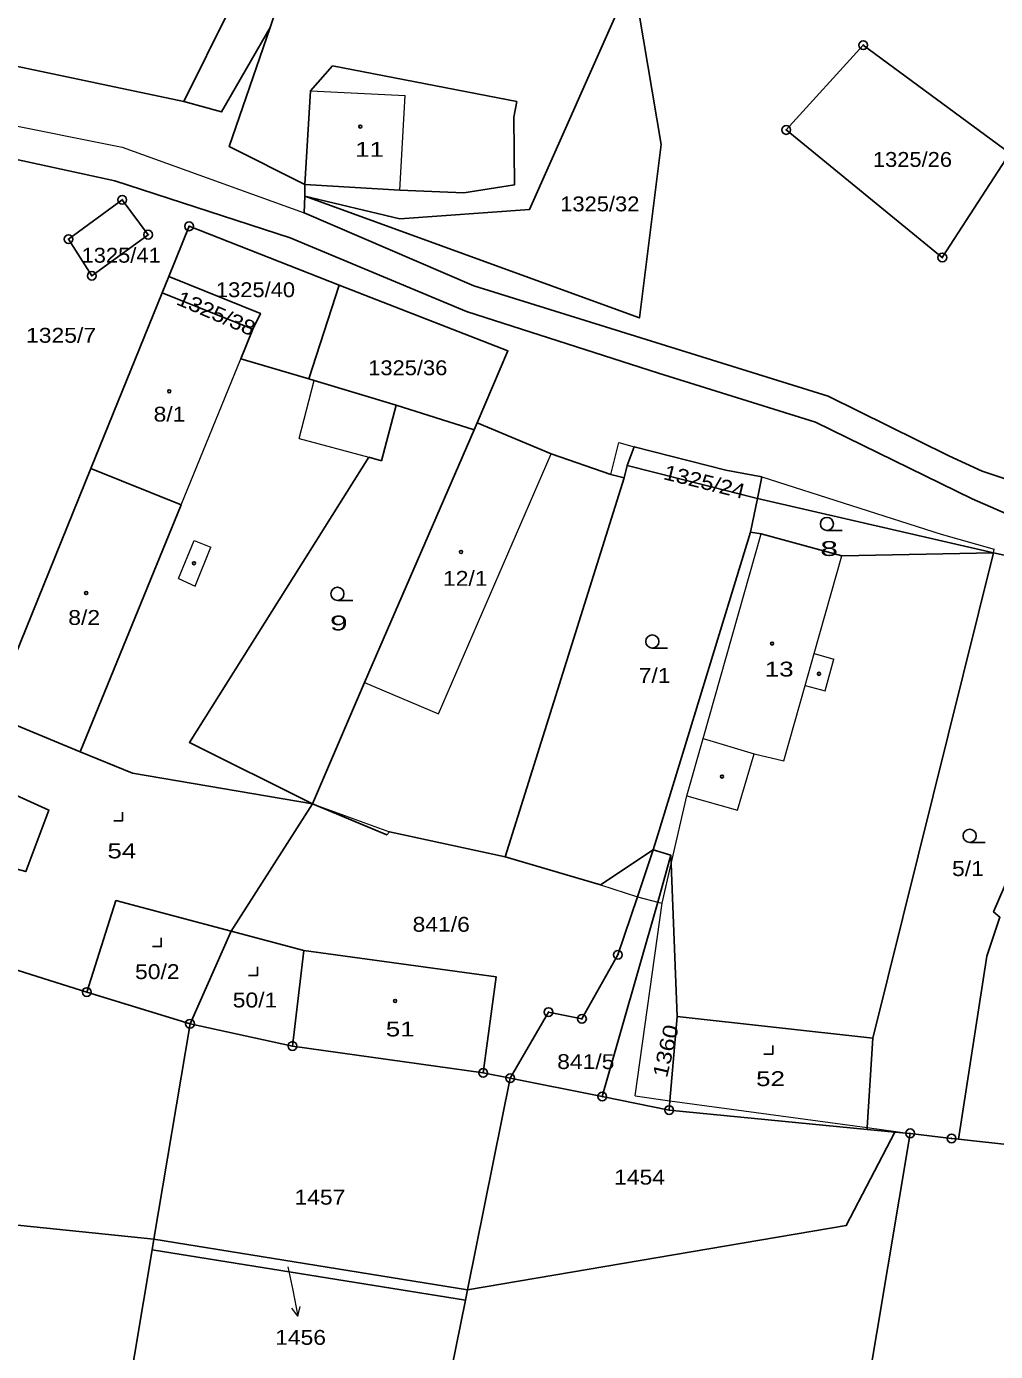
# Model space of a CAD drawing. Extents: x -872229 to -869198, y -1075981 to -1074329.
# Drawn here: x -871035 to -870924.3, y -1075369.5 to -1075218 of the extents above; entities that cross this region are included whole.
import ezdxf
from ezdxf.enums import TextEntityAlignment as Align

# ---------------------------------------------------------------- set-up
doc = ezdxf.new("R2010")
doc.units = 0
doc.header["$LTSCALE"] = 0.68
for name, color, linetype, lineweight in [('1', 7, 'Continuous', 25), ('3', 7, 'Continuous', 25), ('4', 7, 'Continuous', 13), ('5', 7, 'Continuous', 25), ('7', 7, 'Continuous', 13), ('8', 7, 'Continuous', 25)]:
    doc.layers.add(name, color=color, linetype=linetype, lineweight=lineweight)
doc.layers.add('2', color=7, linetype='Continuous')

msp = doc.modelspace()

# ---------------------------------------------------------------- linework, layer by layer
at = {"layer": '1'}
for p, q in [((-871016.45, -1075240.85), (-870999.29, -1075247.56)), ((-870992.78, -1075261.29), (-870994.47, -1075267.64)), ((-870983.88, -1075264.11), (-870983.54, -1075263.33)), ((-870994.47, -1075267.64), (-870995.91, -1075267.25)), ((-870966.4, -1075268.2), (-870966.72, -1075269.58)), ((-870966.4, -1075268.2), (-870951.52, -1075271.96)), ((-871027.67, -1075268.54), (-871039.08, -1075296.69)), ((-870910.7, -1075281.16), (-870924.55, -1075278.18)), ((-871011.62, -1075321.4), (-871002.34, -1075306.85)), ((-870961.39, -1075312.74), (-870963.43, -1075312.12)), ((-871028.14, -1075328.37), (-871016.34, -1075331.99)), ((-871016.34, -1075331.99), (-871020.46, -1075356.63)), ((-871004.64, -1075334.54), (-870982.84, -1075337.6)), ((-870982.84, -1075337.6), (-870979.75, -1075338.22)), ((-870979.75, -1075338.22), (-870984.62, -1075362.41)), ((-870979.75, -1075338.22), (-870969.24, -1075340.31)), ((-870935.8, -1075344.38), (-870938.97, -1075344.07)), ((-870934.07, -1075344.52), (-870935.8, -1075344.38)), ((-870921.99, -1075345.91), (-870928.54, -1075345.19))]:
    msp.add_line(p, q, dxfattribs=at)
for points in [[(-871001.53, -1075179.18), (-871004.71, -1075177.87), (-871056.06, -1075184.2), (-871061.68, -1075207.72), (-871062.03, -1075210.19), (-871063.04, -1075217.35), (-871059.26, -1075218.39), (-871047.62, -1075220.14), (-871017.06, -1075226.57)], [(-871017.06, -1075226.57), (-871011.81, -1075216.07), (-871003.35, -1075187.3), (-871001.53, -1075179.18)], [(-871007.2, -1075218.13), (-871001.24, -1075200.4), (-870998.8, -1075193.31)], [(-871003.22, -1075237.41), (-870964.99, -1075251.33), (-870962.5, -1075231.49), (-870966.06, -1075210.48)], [(-870966.06, -1075210.48), (-870966.78, -1075214.64), (-870977.55, -1075238.93), (-870992.35, -1075240.01), (-871003.22, -1075237.41)], [(-871017.06, -1075226.57), (-871012.74, -1075227.78), (-871007.2, -1075218.13)], [(-871003.22, -1075237.41), (-871003.21, -1075236.08), (-871011.88, -1075231.73), (-871007.2, -1075218.13)], [(-870992.35, -1075236.73), (-870985.06, -1075237.04), (-870979.25, -1075236.1), (-870979.36, -1075228.37), (-870979.01, -1075226.59), (-871000.06, -1075222.52), (-871002.59, -1075225.35)], [(-871002.59, -1075225.35), (-871003.21, -1075236.08), (-870992.35, -1075236.73)], [(-871072.01, -1075232.97), (-871066.83, -1075229.86), (-871050.73, -1075230.05), (-871024.91, -1075235.65), (-871004.91, -1075242.17), (-870984.75, -1075250.58), (-870962.8, -1075257.63), (-870944.86, -1075263.23), (-870926.98, -1075271.99), (-870918.87, -1075275.55), (-870910.63, -1075280.9)], [(-871003.22, -1075237.41), (-871003.31, -1075239.31), (-870983.9, -1075247.65), (-870943.43, -1075260.27), (-870929.66, -1075267.08), (-870925.85, -1075268.83), (-870908.47, -1075274.58)], [(-871027.67, -1075268.54), (-871019.53, -1075248.45), (-871018.75, -1075246.57), (-871016.45, -1075240.85)], [(-871009.17, -1075252.62), (-871008.29, -1075250.81), (-871018.75, -1075246.57)], [(-871002.78, -1075258.3), (-871010.54, -1075255.98), (-871009.17, -1075252.62), (-871019.53, -1075248.45)], [(-870983.54, -1075263.33), (-870980.02, -1075255.1), (-870999.29, -1075247.56), (-871002.78, -1075258.3)], [(-871002.78, -1075258.3), (-871002.16, -1075258.48), (-870992.78, -1075261.29), (-870983.88, -1075264.11)], [(-870968.25, -1075269.2), (-870975.06, -1075266.86), (-870983.54, -1075263.33)], [(-870983.88, -1075264.11), (-870996.4, -1075292.99), (-871002.34, -1075306.85)], [(-870951.52, -1075271.96), (-870951.02, -1075269.49), (-870955.13, -1075268.72), (-870965.59, -1075266.04), (-870966.4, -1075268.2)], [(-870995.91, -1075267.25), (-871016.41, -1075299.83), (-871002.34, -1075306.85)], [(-871028.88, -1075300.9), (-871017.36, -1075272.69), (-871027.67, -1075268.54)], [(-870980.32, -1075312.91), (-870966.72, -1075269.58), (-870968.25, -1075269.2)], [(-870924.55, -1075278.18), (-870951.52, -1075271.96), (-870952.29, -1075275.8)], [(-870952.29, -1075275.8), (-870962.91, -1075310.4), (-870963.43, -1075312.12)], [(-870952.29, -1075275.8), (-870951.09, -1075275.99), (-870941.86, -1075278.5), (-870924.55, -1075278.18)], [(-870961.39, -1075312.74), (-870961.35, -1075313.72), (-870960.69, -1075331.15), (-870938.31, -1075333.64), (-870924.55, -1075278.18)], [(-871028.88, -1075300.9), (-871039.08, -1075296.69), (-871041.74, -1075303.38)], [(-871002.34, -1075306.85), (-871022.9, -1075303.35), (-871028.88, -1075300.9)], [(-871041.74, -1075303.38), (-871032.46, -1075307.57), (-871035.1, -1075314.6), (-871039.25, -1075313.47), (-871042.54, -1075323.84), (-871028.14, -1075328.37)], [(-870980.32, -1075312.91), (-870993.53, -1075310.04), (-870993.87, -1075310.41), (-871002.34, -1075306.85)], [(-870919.9, -1075308.44), (-870924.53, -1075319.22), (-870923.81, -1075319.83), (-870925.29, -1075324.27), (-870928.54, -1075345.19)], [(-870963.43, -1075312.12), (-870969.45, -1075316.11), (-870980.32, -1075312.91)], [(-870979.75, -1075338.22), (-870975.38, -1075330.66), (-870971.56, -1075331.43), (-870967.45, -1075324.11), (-870965.22, -1075317.48), (-870963.43, -1075312.12)], [(-870969.24, -1075340.31), (-870962.91, -1075318.08), (-870961.39, -1075312.74)], [(-871011.62, -1075321.4), (-871024.8, -1075317.92), (-871028.14, -1075328.37)], [(-870982.84, -1075337.6), (-870981.38, -1075326.63), (-871003.32, -1075323.62)], [(-870960.69, -1075331.15), (-870961.51, -1075340.79), (-870961.6, -1075341.86)], [(-870938.97, -1075344.07), (-870938.96, -1075343.86), (-870938.31, -1075333.64)], [(-870938.97, -1075344.07), (-870961.6, -1075341.86), (-870969.24, -1075340.31)], [(-870935.8, -1075344.38), (-870941.36, -1075355.05), (-870984.62, -1075362.41), (-870984.86, -1075363.6)], [(-870928.54, -1075345.19), (-870929.33, -1075345.1), (-870934.07, -1075344.52), (-870949.31, -1075435.5)], [(-871074.84, -1075352.78), (-871055.34, -1075353.05), (-871020.46, -1075356.63)], [(-870984.62, -1075362.41), (-871020.46, -1075356.63), (-871020.66, -1075357.83)], [(-870984.86, -1075363.6), (-871020.66, -1075357.83), (-871029.72, -1075411.9), (-871030.15, -1075414.48), (-871030.73, -1075417.93), (-871031.77, -1075424.14), (-870998.3, -1075429.88)], [(-870984.86, -1075363.6), (-870998.3, -1075429.88), (-870949.31, -1075435.5)]]:
    msp.add_lwpolyline(points, dxfattribs=at)
for points in [[(-870939.42, -1075220.15), (-870948.22, -1075229.84), (-870930.39, -1075244.42), (-870922.66, -1075232.5)], [(-871024.08, -1075237.82), (-871030.22, -1075242.32), (-871027.55, -1075246.5), (-871021.12, -1075241.81)], [(-871011.62, -1075321.4), (-871016.34, -1075331.99), (-871004.64, -1075334.54), (-871003.32, -1075323.62)]]:
    msp.add_lwpolyline(points, close=True, dxfattribs=at)
at = {"layer": '3'}
for p, q in [((-870943.573, -1075275.62), (-870941.823, -1075275.62)), ((-870999.503, -1075283.61), (-870997.753, -1075283.61)), ((-870963.523, -1075289.05), (-870961.773, -1075289.05)), ((-870927.263, -1075311.26), (-870925.513, -1075311.26))]:
    msp.add_line(p, q, dxfattribs=at)
for points in [[(-871025.061, -1075308.81), (-871024.06, -1075308.81), (-871024.06, -1075307.81)], [(-871020.621, -1075323.18), (-871019.62, -1075323.18), (-871019.62, -1075322.18)], [(-871009.641, -1075326.48), (-871008.64, -1075326.48), (-871008.64, -1075325.48)], [(-870950.771, -1075335.46), (-870949.77, -1075335.46), (-870949.77, -1075334.46)]]:
    msp.add_lwpolyline(points, dxfattribs=at)
for centre in [(-870943.5729, -1075274.8698), (-870999.5029, -1075282.8598), (-870963.5229, -1075288.2998), (-870927.2629, -1075310.5098)]:
    msp.add_circle(centre, 0.75, dxfattribs=at)
at = {"layer": '4'}
for p, q in [((-871002.59, -1075225.35), (-870991.76, -1075225.89)), ((-870992.35, -1075236.73), (-870991.76, -1075225.89)), ((-871050.04, -1075226.59), (-871024.09, -1075231.8)), ((-871024.09, -1075231.8), (-871003.31, -1075239.31)), ((-871017.36, -1075272.69), (-871010.54, -1075255.98)), ((-871003.86, -1075265.1), (-871002.16, -1075258.48)), ((-871003.86, -1075265.1), (-870995.91, -1075267.25)), ((-870987.95, -1075296.59), (-870975.06, -1075266.86)), ((-870951.02, -1075269.49), (-870930.53, -1075276.05)), ((-871017.66, -1075281.11), (-871015.85, -1075276.76)), ((-871015.85, -1075276.76), (-871013.96, -1075277.53)), ((-870930.53, -1075276.05), (-870924.46, -1075277.76)), ((-871015.77, -1075281.98), (-871013.96, -1075277.53)), ((-870945.03, -1075289.68), (-870941.86, -1075278.5)), ((-870924.55, -1075278.18), (-870924.46, -1075277.76)), ((-871017.66, -1075281.11), (-871015.77, -1075281.98)), ((-870943.79, -1075293.95), (-870942.77, -1075290.32)), ((-870996.4, -1075292.99), (-870987.95, -1075296.59)), ((-870957.71, -1075299.39), (-870951.87, -1075301.13)), ((-871002.34, -1075306.85), (-870993.53, -1075310.04)), ((-870969.45, -1075316.11), (-870965.22, -1075317.48)), ((-870965.47, -1075340.25), (-870962.39, -1075318.22)), ((-870965.47, -1075340.25), (-870961.51, -1075340.79)), ((-870961.51, -1075340.79), (-870938.96, -1075343.86)), ((-870938.96, -1075343.86), (-870934.07, -1075344.52))]:
    msp.add_line(p, q, dxfattribs=at)
for points in [[(-870968.25, -1075269.2), (-870967.36, -1075265.55), (-870965.59, -1075266.04)], [(-870959.56, -1075305.94), (-870957.71, -1075299.39), (-870951.09, -1075275.99)], [(-870946.07, -1075293.33), (-870945.03, -1075289.68), (-870942.77, -1075290.32)], [(-870948.51, -1075301.94), (-870946.07, -1075293.33), (-870943.79, -1075293.95)], [(-870953.78, -1075307.6), (-870951.87, -1075301.13), (-870948.51, -1075301.94)], [(-870961.35, -1075313.72), (-870959.56, -1075305.94), (-870953.78, -1075307.6)], [(-870965.22, -1075317.48), (-870962.91, -1075318.08), (-870962.39, -1075318.22), (-870961.35, -1075313.72)]]:
    msp.add_lwpolyline(points, dxfattribs=at)
at = {"layer": '5'}
for centre in [(-870996.8868, -1075229.4492), (-871018.7168, -1075259.7092), (-870985.3768, -1075278.0692), (-871015.8768, -1075279.3592), (-871028.2068, -1075282.7692), (-870949.8368, -1075288.5392), (-870944.4768, -1075291.9992), (-870955.5568, -1075303.7392), (-870992.9068, -1075329.3892)]:
    msp.add_circle(centre, 0.175, dxfattribs=at)
at = {"layer": '7'}
msp.add_line((-871004.037, -1075365.406), (-871003.737, -1075364.327), dxfattribs=at)
msp.add_lwpolyline([(-871005.15, -1075359.79), (-871004.61, -1075362.46), (-871004.037, -1075365.406), (-871004.72, -1075364.518)], dxfattribs=at)
at = {"layer": '8'}
for centre, radius in [((-870939.42, -1075220.1499), 0.5), ((-870939.42, -1075220.1499), 0.0303), ((-870948.22, -1075229.8399), 0.5), ((-870948.22, -1075229.8399), 0.0303), ((-871024.08, -1075237.8199), 0.5), ((-871024.08, -1075237.8199), 0.0303), ((-871016.45, -1075240.8499), 0.5), ((-871016.45, -1075240.8499), 0.0303), ((-871030.22, -1075242.3199), 0.5), ((-871030.22, -1075242.3199), 0.0303), ((-871021.12, -1075241.8099), 0.5), ((-871021.12, -1075241.8099), 0.0303), ((-870930.39, -1075244.4199), 0.5), ((-870930.39, -1075244.4199), 0.0303), ((-871027.55, -1075246.4999), 0.5), ((-871027.55, -1075246.4999), 0.0303), ((-870967.45, -1075324.1099), 0.5), ((-870967.45, -1075324.1099), 0.0303), ((-871028.14, -1075328.3699), 0.5), ((-871028.14, -1075328.3699), 0.0303), ((-870975.38, -1075330.6599), 0.5), ((-871016.34, -1075331.9899), 0.5), ((-870975.38, -1075330.6599), 0.0303), ((-870971.56, -1075331.4299), 0.5), ((-870971.56, -1075331.4299), 0.0303), ((-871016.34, -1075331.9899), 0.0303), ((-871004.64, -1075334.5399), 0.5), ((-871004.64, -1075334.5399), 0.0303), ((-870982.84, -1075337.5999), 0.5), ((-870982.84, -1075337.5999), 0.0303), ((-870979.75, -1075338.2199), 0.5), ((-870979.75, -1075338.2199), 0.0303), ((-870969.24, -1075340.3099), 0.5), ((-870969.24, -1075340.3099), 0.0303), ((-870961.6, -1075341.8599), 0.5), ((-870961.6, -1075341.8599), 0.0303), ((-870934.07, -1075344.5199), 0.5), ((-870934.07, -1075344.5199), 0.0303), ((-870929.33, -1075345.0999), 0.5), ((-870929.33, -1075345.0999), 0.0303)]:
    msp.add_circle(centre, radius, dxfattribs=at)

# ---------------------------------------------------------------- texts
at = {"layer": '2'}
for s, width, p in [('11', 1.3, (-870997.47, -1075232.91)), ('1325/26', 1.1, (-870938.32, -1075234.06)), ('1325/32', 1.1, (-870974.04, -1075239.14)), ('1325/41', 1.1, (-871028.73, -1075245.01)), ('1325/7', 1.15, (-871035.07, -1075254.16)), ('1325/36', 1.1, (-870995.98, -1075257.87)), ('8/1', 1.15, (-871020.5, -1075263.17)), ('8', 1.6, (-870944.33, -1075278.53)), ('12/1', 1.15, (-870987.44, -1075281.94)), ('8/2', 1.15, (-871030.25, -1075286.41)), ('9', 1.6, (-871000.35, -1075287.04)), ('13', 1.3, (-870950.67, -1075292.31)), ('7/1', 1.15, (-870965.08, -1075293.04)), ('54', 1.3, (-871025.77, -1075313.09)), ('5/1', 1.15, (-870929.28, -1075315.11)), ('841/6', 1.15, (-870990.91, -1075321.48)), ('50/2', 1.15, (-871022.62, -1075326.89)), ('50/1', 1.15, (-871011.46, -1075330.13)), ('51', 1.3, (-870993.97, -1075333.45)), ('841/5', 1.15, (-870974.39, -1075337.17)), ('52', 1.3, (-870951.66, -1075339.12)), ('1454', 1.15, (-870967.89, -1075350.38)), ('1457', 1.15, (-871004.41, -1075352.67))]:
    msp.add_text(s, height=1.7, dxfattribs=dict(at, width=width)).set_placement(p)
for s, rotation, width, p in [('1325/38', 337, 1.15, (-871018.032, -1075249.732)), ('1325/24', 346, 1.15, (-870962.355, -1075269.734)), ('1360', 77, 1.2, (-870961.851, -1075338.251))]:
    msp.add_text(s, height=1.7, rotation=rotation, dxfattribs=dict(at, width=width)).set_placement(p)
for s, width, p in [('1325/40', 1.1, (-871008.859, -1075248.95)), ('1456', 1.15, (-871003.71, -1075368.69))]:
    msp.add_text(s, height=1.7, dxfattribs=dict(at, width=width)).set_placement(p, align=Align.CENTER)

doc.saveas('drawing.dxf')
